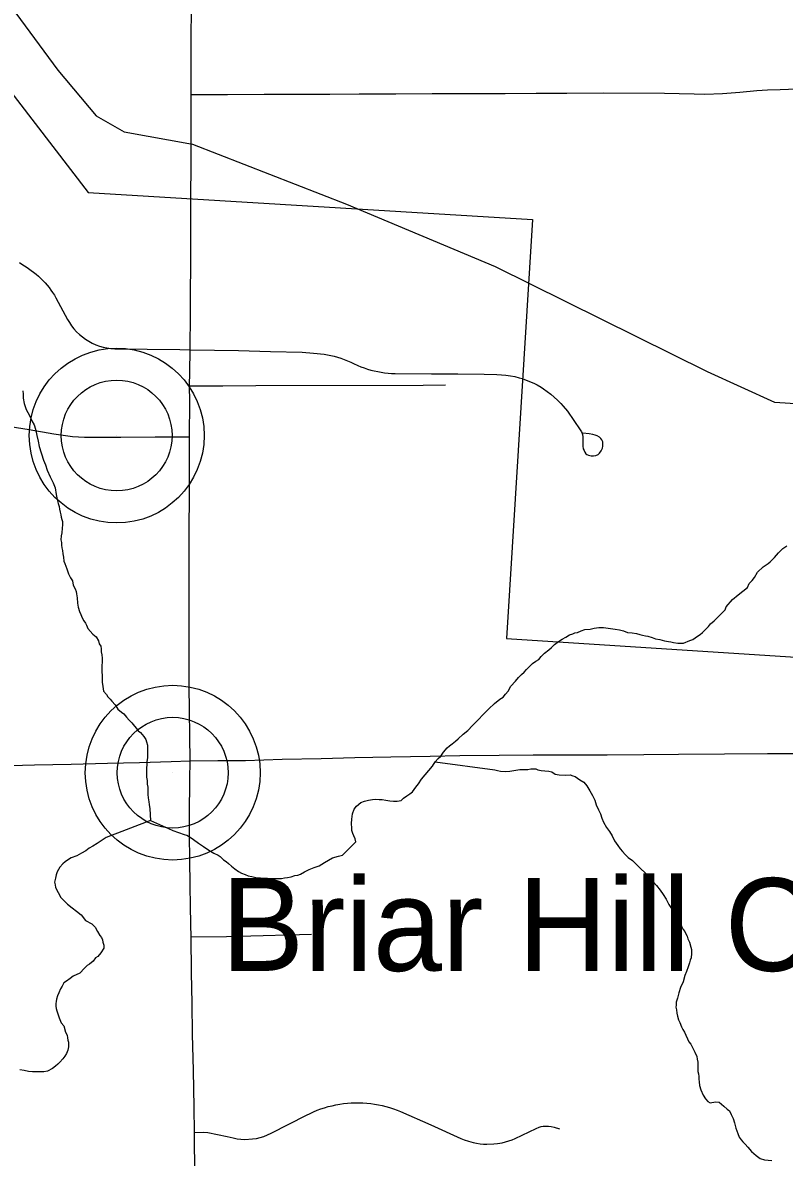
# Model space of a CAD drawing. Extents: x -11.4 to 84.1, y 11.1 to 59.
# Drawn here: x 28.325 to 28.973, y 45.628 to 46.596 of the extents above; entities that cross this region are included whole.
import ezdxf

# ---------------------------------------------------------------- set-up
doc = ezdxf.new("R2010")
doc.units = 0
for name, color, linetype in [('GM_X_Corporation', 7, 'Continuous'), ('GM_X_County_Road', 7, 'Continuous'), ('GM_X_Major_River', 7, 'Continuous'), ('GM_X_Minor_River', 7, 'Continuous'), ('GM_X_Rail_Line', 7, 'Continuous'), ('GM_X_State_Route', 7, 'Continuous'), ('GM_X_Township_Road', 7, 'Continuous'), ('GM_X_Unincorporated', 7, 'Continuous'), ('GM_X_Unincorporated_Location', 7, 'Continuous'), ('GM_X_Unincorporated_Text', 7, 'Continuous')]:
    doc.layers.add(name, color=color, linetype=linetype)

msp = doc.modelspace()

# ---------------------------------------------------------------- linework, layer by layer
at = {"layer": 'GM_X_Corporation'}
msp.add_lwpolyline([(28.25971, 46.6087), (28.38036, 46.45198), (28.75842, 46.42895), (28.73636, 46.07221), (29.25462, 46.0387), (29.28069, 46.4633), (29.48694, 46.4478)], dxfattribs=at)
at = {"layer": 'GM_X_County_Road'}
for points in [[(28.4671, 45.96801), (28.49064, 45.96824), (28.51419, 45.96847), (28.54524, 45.96936), (28.57848, 45.97013), (28.60711, 45.97079), (28.63782, 45.97132), (28.6713, 45.9719), (28.69658, 45.97255), (28.73007, 45.97288), (28.75893, 45.97317), (28.79056, 45.97306), (28.82196, 45.97317), (28.85314, 45.97352), (28.88269, 45.97363), (28.92183, 45.97387), (28.95842, 45.97421), (28.9926, 45.97437)], [(28.30368, 45.96376), (28.33474, 45.96453), (28.36579, 45.9653), (28.39685, 45.96608), (28.42385, 45.96675), (28.45086, 45.96742), (28.4671, 45.96801)]]:
    msp.add_lwpolyline(points, dxfattribs=at)
at = {"layer": 'GM_X_Major_River'}
for points in [[(28.67555, 45.96706), (28.67815, 45.97015), (28.6804, 45.97209), (28.68262, 45.97554), (28.6856, 45.97902), (28.68785, 45.98095), (28.6901, 45.98251), (28.69272, 45.98484), (28.69497, 45.98677), (28.69946, 45.99065), (28.70321, 45.99376), (28.70731, 45.998), (28.71179, 46.00264), (28.71665, 46.00767), (28.72113, 46.0123), (28.72599, 46.01695), (28.73049, 46.02044), (28.73349, 46.02239), (28.73535, 46.0247), (28.73759, 46.0274), (28.73979, 46.03162), (28.7439, 46.03587), (28.74651, 46.03896), (28.74912, 46.04166), (28.75137, 46.0436), (28.75323, 46.04591), (28.75622, 46.049), (28.75846, 46.05094), (28.76109, 46.05289), (28.76372, 46.05445), (28.76558, 46.05676), (28.76857, 46.05985), (28.77232, 46.06258), (28.77457, 46.06452), (28.77718, 46.06722), (28.78056, 46.06956), (28.78357, 46.07151), (28.78657, 46.07346), (28.78996, 46.07542), (28.7926, 46.07622), (28.79449, 46.07701), (28.79676, 46.07743), (28.79978, 46.07862), (28.8028, 46.07981), (28.80735, 46.08027), (28.81075, 46.08108), (28.81492, 46.08153), (28.81872, 46.08159), (28.82862, 46.08024), (28.83243, 46.07954), (28.83586, 46.07883), (28.8393, 46.07737), (28.84311, 46.07705), (28.84692, 46.07635), (28.84959, 46.07564), (28.85188, 46.07491), (28.85454, 46.07458), (28.85645, 46.07423), (28.86026, 46.07315), (28.86294, 46.07206), (28.86675, 46.07136), (28.87057, 46.07028), (28.874, 46.06957), (28.8759, 46.06923), (28.87819, 46.06888), (28.882, 46.06818), (28.88428, 46.06822), (28.88693, 46.06827), (28.89221, 46.07063), (28.89486, 46.07144), (28.89861, 46.07416), (28.90086, 46.07572), (28.90311, 46.07728), (28.90498, 46.07921), (28.90797, 46.0823), (28.90983, 46.08461), (28.91282, 46.08732), (28.91582, 46.09004), (28.91768, 46.09197), (28.91955, 46.0939), (28.92216, 46.0966), (28.92325, 46.09928), (28.92847, 46.10545), (28.93334, 46.10934), (28.94122, 46.11555), (28.94268, 46.119), (28.94529, 46.1217), (28.94715, 46.12401), (28.94973, 46.12862), (28.95459, 46.13326), (28.95872, 46.13599), (28.9606, 46.13754), (28.96247, 46.13948), (28.96434, 46.14103), (28.96768, 46.14527), (28.97143, 46.14875), (28.9748, 46.15109)], [(28.43346, 45.91734), (28.4486, 45.91047), (28.45243, 45.90863), (28.46198, 45.90537), (28.46427, 45.90465), (28.46695, 45.90317), (28.47003, 45.90094), (28.47426, 45.89797), (28.47849, 45.895), (28.48309, 45.89203), (28.48732, 45.88944), (28.49076, 45.88759), (28.49268, 45.88648), (28.49539, 45.88387), (28.49769, 45.88238), (28.49962, 45.88051), (28.50232, 45.87827), (28.50501, 45.87604), (28.50809, 45.87381), (28.51077, 45.87233), (28.51383, 45.87124), (28.5165, 45.87014), (28.51956, 45.86943), (28.52299, 45.86873), (28.52679, 45.86841), (28.53287, 45.86813), (28.53668, 45.86781), (28.54237, 45.86791), (28.54465, 45.86794), (28.5473, 45.86837), (28.54995, 45.86879), (28.55298, 45.86922), (28.556, 45.87041), (28.55866, 45.87084), (28.56092, 45.87163), (28.56431, 45.87359), (28.56845, 45.87556), (28.5726, 45.87715), (28.57675, 45.87874), (28.58127, 45.88148), (28.58804, 45.88539), (28.59333, 45.887), (28.59673, 45.88781), (28.60794, 45.89902), (28.60752, 45.90168), (28.60633, 45.90432), (28.60554, 45.90621), (28.60474, 45.90886), (28.6047, 45.91076), (28.60426, 45.91456), (28.60458, 45.91836), (28.60492, 45.92065), (28.60526, 45.92294), (28.60672, 45.92676), (28.60857, 45.92946), (28.61232, 45.93256), (28.61533, 45.93375), (28.61874, 45.93457), (28.62215, 45.935), (28.62518, 45.93543), (28.62785, 45.9351), (28.6305, 45.93514), (28.63355, 45.93443), (28.63698, 45.93411), (28.64002, 45.93377), (28.64306, 45.93383), (28.64647, 45.93426), (28.64872, 45.9362), (28.65134, 45.93814), (28.65397, 45.94009), (28.65622, 45.94165), (28.6592, 45.9455), (28.66143, 45.94858), (28.66402, 45.95242), (28.67333, 45.9636), (28.67555, 45.96706)], [(28.43346, 45.91734), (28.39555, 45.90276), (28.39217, 45.90042), (28.38804, 45.89769), (28.38428, 45.89535), (28.38127, 45.89378), (28.37827, 45.89145), (28.3745, 45.88948), (28.37075, 45.88714), (28.36584, 45.88554), (28.36283, 45.88359), (28.36058, 45.88203), (28.3587, 45.88048), (28.3561, 45.87739), (28.35388, 45.87355), (28.35317, 45.87088), (28.35245, 45.8682), (28.35175, 45.86477), (28.35217, 45.8625), (28.35259, 45.86022), (28.35691, 45.85155), (28.35922, 45.8493), (28.3627, 45.84594), (28.36655, 45.84296), (28.3704, 45.83998), (28.37425, 45.837), (28.37813, 45.83212), (28.38349, 45.82917), (28.38619, 45.82655), (28.38816, 45.82278), (28.39011, 45.81939), (28.39166, 45.81752), (28.39246, 45.81563), (28.39287, 45.81373), (28.39367, 45.81108), (28.39372, 45.80842), (28.39112, 45.80458), (28.38851, 45.80149), (28.38664, 45.80032), (28.3844, 45.79762), (28.38141, 45.79491), (28.37953, 45.79374), (28.37729, 45.79142), (28.37318, 45.78717), (28.36753, 45.7848), (28.3649, 45.78285), (28.3619, 45.78052), (28.35965, 45.77896), (28.35817, 45.77628), (28.35669, 45.77397), (28.35523, 45.77052), (28.35414, 45.76784), (28.35342, 45.76517), (28.35307, 45.76326), (28.35272, 45.76136), (28.35276, 45.75908), (28.35318, 45.75718), (28.35358, 45.75529), (28.35439, 45.75264), (28.35559, 45.74924), (28.35718, 45.74508), (28.3595, 45.74245), (28.36111, 45.73716), (28.36229, 45.73452), (28.36271, 45.73224), (28.36312, 45.73035), (28.36353, 45.72845), (28.3636, 45.72465), (28.36289, 45.7216), (28.36179, 45.71892), (28.36031, 45.71661), (28.35883, 45.71431), (28.35622, 45.7116), (28.35435, 45.70967), (28.35248, 45.70812), (28.34985, 45.70617), (28.34571, 45.70382), (28.34268, 45.70339), (28.33964, 45.70334), (28.33661, 45.70329), (28.33281, 45.70323), (28.32939, 45.70355), (28.32595, 45.70426), (28.32215, 45.70496)]]:
    msp.add_lwpolyline(points, dxfattribs=at)
at = {"layer": 'GM_X_Minor_River'}
for points in [[(28.3246, 46.28299), (28.32503, 46.28034), (28.32508, 46.27691), (28.32592, 46.27237), (28.32753, 46.26707), (28.33027, 46.26217), (28.33224, 46.25764), (28.3342, 46.25425), (28.3354, 46.25047), (28.33663, 46.24516), (28.33785, 46.24024), (28.33869, 46.23569), (28.3423, 46.22396), (28.34389, 46.22018), (28.34548, 46.21565), (28.34786, 46.20998), (28.3506, 46.2047), (28.35219, 46.20055), (28.35305, 46.19486), (28.35388, 46.19069), (28.35469, 46.18728), (28.3555, 46.18463), (28.35592, 46.18236), (28.35634, 46.1797), (28.35714, 46.17743), (28.35717, 46.17553), (28.35796, 46.17364), (28.35838, 46.17175), (28.35842, 46.16909), (28.35809, 46.16604), (28.35777, 46.16223), (28.35744, 46.15956), (28.35712, 46.15614), (28.35754, 46.15386), (28.35757, 46.15158), (28.35799, 46.14931), (28.35841, 46.14703), (28.35883, 46.14438), (28.35926, 46.14134), (28.3597, 46.13793), (28.36049, 46.13604), (28.36129, 46.13377), (28.36209, 46.1315), (28.36368, 46.12735), (28.36525, 46.12395), (28.36682, 46.12131), (28.36764, 46.11752), (28.36921, 46.11451), (28.37001, 46.11224), (28.37042, 46.11034), (28.37086, 46.10693), (28.37131, 46.10238), (28.37175, 46.09896), (28.37295, 46.09518), (28.37414, 46.09253), (28.37532, 46.08989), (28.3765, 46.08725), (28.37805, 46.08538), (28.37885, 46.08349), (28.38003, 46.08084), (28.38429, 46.07597), (28.38699, 46.07373), (28.38894, 46.07034), (28.38975, 46.06769), (28.39092, 46.06581), (28.39133, 46.06354), (28.39138, 46.06088), (28.3918, 46.05822), (28.39223, 46.05557), (28.39229, 46.05215), (28.39196, 46.0491), (28.392, 46.04644), (28.39205, 46.0434), (28.39209, 46.04111), (28.39214, 46.03845), (28.39219, 46.03503), (28.39264, 46.03124), (28.39305, 46.02934), (28.39346, 46.02745), (28.39579, 46.02445), (28.39696, 46.02256), (28.39889, 46.02069), (28.40044, 46.01882), (28.40315, 46.01582), (28.40549, 46.01206), (28.40858, 46.00944), (28.4105, 46.00795), (28.41282, 46.00533), (28.41515, 46.00271), (28.41746, 46.00046), (28.41979, 45.99746), (28.42134, 45.99559), (28.42289, 45.99371), (28.42482, 45.99222), (28.42753, 45.98884), (28.42948, 45.98621)], [(28.42948, 45.98621), (28.42989, 45.98432), (28.4307, 45.98129), (28.43074, 45.97901), (28.43079, 45.97559), (28.43088, 45.97064), (28.43017, 45.96759), (28.43021, 45.96493), (28.42989, 45.96188), (28.42996, 45.9577), (28.43001, 45.95428), (28.43044, 45.95124), (28.43049, 45.9482), (28.43092, 45.94555), (28.43097, 45.94251), (28.43102, 45.93946), (28.43145, 45.93643), (28.43189, 45.93302), (28.43231, 45.93074), (28.43274, 45.92732), (28.43346, 45.91734)], [(28.67555, 45.96706), (28.72618, 45.96029), (28.72846, 45.95995), (28.73113, 45.95923), (28.7357, 45.95892), (28.73911, 45.95936), (28.74744, 45.96064), (28.75086, 45.9607), (28.75428, 45.96075), (28.75693, 45.96118), (28.75921, 45.96121), (28.76111, 45.96124), (28.76302, 45.96052), (28.76569, 45.9598), (28.76873, 45.95947), (28.77216, 45.95914), (28.77482, 45.95881), (28.77752, 45.95657), (28.78094, 45.95625), (28.78626, 45.95595), (28.79044, 45.95602), (28.79273, 45.9553), (28.79464, 45.95457), (28.79849, 45.95197), (28.80194, 45.94975), (28.80465, 45.94675), (28.807, 45.94261), (28.80935, 45.93846), (28.81131, 45.93469), (28.81252, 45.93053), (28.81449, 45.92638), (28.81606, 45.92298), (28.81727, 45.9192), (28.81884, 45.9158), (28.8212, 45.91128), (28.82391, 45.9079), (28.82625, 45.90414), (28.82822, 45.89999), (28.83095, 45.89585), (28.8329, 45.89322), (28.83483, 45.89097), (28.83715, 45.88834), (28.83986, 45.88573), (28.84332, 45.88312), (28.84679, 45.87976), (28.85027, 45.87639), (28.85413, 45.87265), (28.86109, 45.86516), (28.86381, 45.86178), (28.86691, 45.85803), (28.86963, 45.85427), (28.87198, 45.85013), (28.87433, 45.84561), (28.87667, 45.84222), (28.87861, 45.83959), (28.8802, 45.83544), (28.88215, 45.83242), (28.88372, 45.82941), (28.88529, 45.82677), (28.88646, 45.82451), (28.88801, 45.82263), (28.88881, 45.82075), (28.88998, 45.81887), (28.8904, 45.81659), (28.89197, 45.81357), (28.89317, 45.80941), (28.89359, 45.80752), (28.89364, 45.80409), (28.89333, 45.80029), (28.8926, 45.79837), (28.89188, 45.79608), (28.8908, 45.79264), (28.88934, 45.78881), (28.88788, 45.78537), (28.88645, 45.78002), (28.88425, 45.77504), (28.88281, 45.77045), (28.88175, 45.76587), (28.88067, 45.76243), (28.88071, 45.76015), (28.88036, 45.75825), (28.88078, 45.75597), (28.8812, 45.75332), (28.88162, 45.75066), (28.88243, 45.74763), (28.88361, 45.74537), (28.88519, 45.74159), (28.88637, 45.73933), (28.88755, 45.73707), (28.88873, 45.73443), (28.8903, 45.73141), (28.89149, 45.72877), (28.89304, 45.72689), (28.89657, 45.72011), (28.89815, 45.71633), (28.89857, 45.71405), (28.899, 45.7114), (28.89904, 45.70874), (28.89909, 45.7057), (28.89913, 45.70342), (28.89954, 45.70152)], [(28.89954, 45.70152), (28.89996, 45.69925), (28.9, 45.69697), (28.90004, 45.69468), (28.90047, 45.69165), (28.90167, 45.68787), (28.90364, 45.68334), (28.90559, 45.68033), (28.90753, 45.67808), (28.90945, 45.67697), (28.91399, 45.6778), (28.91704, 45.67747), (28.92127, 45.67412), (28.92397, 45.6715), (28.9259, 45.67001), (28.92747, 45.667), (28.92904, 45.6636), (28.93025, 45.65982), (28.93146, 45.65527), (28.93306, 45.65074), (28.93425, 45.64772), (28.9358, 45.64546), (28.93736, 45.64358), (28.93929, 45.64171), (28.94161, 45.63909), (28.94471, 45.63534), (28.94856, 45.63198), (28.95203, 45.62938), (28.95584, 45.6283), (28.96193, 45.62764)]]:
    msp.add_lwpolyline(points, dxfattribs=at)
at = {"layer": 'GM_X_Rail_Line'}
msp.add_lwpolyline([(27.87133, 47.41026), (28.31469, 46.60998), (28.35442, 46.5561), (28.38709, 46.51724), (28.411, 46.50365), (28.46901, 46.49304), (28.59999, 46.44188), (28.7266, 46.38884), (28.90686, 46.29962), (28.96424, 46.27341), (29.02225, 46.26967), (29.04408, 46.28589), (29.07776, 46.34829), (29.09959, 46.38323), (29.13452, 46.40756), (29.16446, 46.41567), (29.23369, 46.40569), (29.32475, 46.39009), (29.40646, 46.38884)], dxfattribs=at)
at = {"layer": 'GM_X_State_Route'}
for points in [[(28.4671, 45.96801), (28.46678, 45.98943), (28.46646, 46.01084), (28.46632, 46.03174), (28.46617, 46.05264), (28.46627, 46.08371), (28.46636, 46.11477), (28.4664, 46.2439), (28.46666, 46.27404), (28.46662, 46.28727), (28.46686, 46.29901), (28.467, 46.31811), (28.46725, 46.34917), (28.46741, 46.36859), (28.46757, 46.38801), (28.4678, 46.5353), (28.46794, 46.56637), (28.46803, 46.58602), (28.46811, 46.60567), (28.46823, 46.61662)], [(28.47114, 45.6232), (28.47082, 45.64282), (28.47077, 45.65173), (28.47041, 45.6732), (28.46978, 45.70427), (28.46916, 45.73533), (28.46863, 45.76152), (28.46809, 45.78772), (28.46801, 45.81831), (28.46762, 45.82873), (28.4673, 45.84497), (28.46698, 45.86121), (28.46675, 45.88477), (28.46657, 45.90363), (28.46646, 45.92173), (28.46675, 45.95229), (28.4671, 45.96801)]]:
    msp.add_lwpolyline(points, dxfattribs=at)
at = {"layer": 'GM_X_Township_Road'}
for points in [[(28.4678, 46.5353), (28.49887, 46.53542), (28.52994, 46.53554), (28.56101, 46.53566), (28.58595, 46.53576), (28.61088, 46.53585), (28.64195, 46.53598), (28.67302, 46.53609), (28.70409, 46.53622), (28.73516, 46.53634), (28.76135, 46.53644), (28.78755, 46.53654), (28.81861, 46.53666), (28.87065, 46.53655), (28.88327, 46.53631), (28.89598, 46.53606)], [(28.89598, 46.53606), (28.90492, 46.53575), (28.92003, 46.53619), (28.93463, 46.53743), (28.94923, 46.53874), (28.95828, 46.5394), (28.96909, 46.53969), (28.98336, 46.54007)], [(28.32192, 46.39231), (28.32467, 46.3904), (28.32742, 46.38859), (28.32964, 46.38715), (28.33182, 46.38564), (28.3339, 46.38405), (28.33599, 46.38237), (28.33798, 46.38063), (28.33992, 46.37883), (28.34176, 46.37696), (28.34357, 46.37502), (28.34532, 46.37302), (28.34698, 46.37097), (28.34854, 46.36885), (28.35005, 46.36668), (28.35152, 46.36446), (28.35289, 46.36219), (28.36274, 46.34389), (28.3643, 46.34119), (28.36615, 46.33844), (28.36818, 46.33585), (28.37041, 46.33338), (28.37278, 46.33108), (28.37534, 46.32896), (28.37799, 46.32702), (28.38079, 46.32528), (28.38372, 46.32372), (28.38675, 46.32237), (28.38988, 46.32124), (28.39305, 46.32033), (28.39628, 46.31965), (28.39954, 46.31919), (28.40286, 46.31896), (28.43055, 46.31865), (28.45825, 46.31834), (28.467, 46.31811)], [(28.467, 46.31811), (28.48767, 46.31775), (28.50833, 46.3174), (28.53539, 46.31666), (28.56246, 46.31593), (28.57205, 46.31515), (28.57503, 46.31496), (28.57797, 46.31468), (28.58095, 46.3143), (28.58384, 46.3138), (28.58678, 46.3132), (28.58967, 46.31252), (28.59252, 46.31172), (28.59536, 46.31082), (28.59815, 46.30982), (28.60095, 46.30874), (28.60365, 46.30755), (28.60597, 46.30645), (28.60962, 46.30476), (28.61236, 46.30362), (28.61516, 46.30258), (28.61796, 46.30164), (28.62085, 46.30079), (28.62368, 46.30005), (28.62662, 46.2994), (28.62951, 46.29886), (28.63245, 46.29841), (28.63543, 46.29808), (28.63837, 46.29784), (28.64136, 46.29771), (28.67243, 46.29754), (28.69488, 46.29741), (28.71734, 46.29728), (28.72811, 46.29691), (28.73195, 46.29677), (28.73574, 46.29644), (28.73953, 46.2959), (28.74327, 46.29518), (28.74696, 46.29425), (28.74943, 46.29353), (28.75303, 46.29228), (28.75658, 46.29085), (28.76004, 46.28924), (28.76231, 46.28805), (28.76558, 46.28614), (28.76776, 46.28478), (28.77089, 46.28258), (28.77387, 46.28023), (28.77676, 46.27773), (28.77951, 46.27507), (28.78233, 46.27228), (28.78441, 46.26998), (28.78804, 46.2657), (28.79901, 46.24984), (28.80005, 46.24803), (28.80076, 46.24589), (28.80106, 46.2438), (28.80118, 46.24065), (28.80108, 46.23782), (28.8012, 46.23607), (28.80159, 46.23377), (28.80219, 46.23218), (28.80274, 46.23097), (28.80371, 46.22953), (28.80466, 46.22878), (28.80609, 46.22817), (28.80828, 46.22779), (28.81015, 46.22768), (28.8122, 46.22787), (28.81426, 46.22888), (28.8154, 46.2299), (28.81688, 46.23197), (28.81786, 46.23431), (28.81827, 46.23607), (28.81805, 46.23958), (28.81733, 46.24134), (28.81642, 46.24252), (28.8153, 46.2437), (28.81327, 46.24485), (28.81157, 46.24545), (28.80967, 46.24601), (28.80664, 46.24641), (28.80104, 46.24693)], [(28.46662, 46.28727), (28.49477, 46.28738), (28.52292, 46.28749), (28.66533, 46.28789), (28.6843, 46.28806)], [(28.30689, 46.25392), (28.33, 46.25017), (28.35098, 46.24646), (28.36687, 46.24414), (28.37711, 46.24355), (28.40818, 46.24367), (28.43729, 46.24378), (28.4664, 46.2439)], [(28.46801, 45.81831), (28.49806, 45.81842), (28.52912, 45.81934), (28.54976, 45.81995), (28.5704, 45.82056)], [(28.47077, 45.65173), (28.47833, 45.65184), (28.48211, 45.65161), (28.49853, 45.64818), (28.50371, 45.64697), (28.50693, 45.64634), (28.51025, 45.64593), (28.51352, 45.64576), (28.52015, 45.6461), (28.52342, 45.64661), (28.52664, 45.64735), (28.52976, 45.64831), (28.53285, 45.64949), (28.53607, 45.65098), (28.55109, 45.65871), (28.56611, 45.66644), (28.5691, 45.6679), (28.57214, 45.66926), (28.57517, 45.67051), (28.57829, 45.67164), (28.58142, 45.67268), (28.58459, 45.6736), (28.58782, 45.67442), (28.59104, 45.67511), (28.59431, 45.6757), (28.59758, 45.67617), (28.60085, 45.67653), (28.60417, 45.67678), (28.60744, 45.6769), (28.61407, 45.67681), (28.61738, 45.67659), (28.62065, 45.67626), (28.62392, 45.67581), (28.62719, 45.67524), (28.63041, 45.67456), (28.63363, 45.67378), (28.63681, 45.67287), (28.63998, 45.67187), (28.64311, 45.67074), (28.64614, 45.66952), (28.67182, 45.65806), (28.69749, 45.6466), (28.70024, 45.64546), (28.70398, 45.64416), (28.70782, 45.64312), (28.71075, 45.64253), (28.71369, 45.64209), (28.71663, 45.64179), (28.71961, 45.64166), (28.72558, 45.64186), (28.72852, 45.64219), (28.73246, 45.64288), (28.73535, 45.64357), (28.73818, 45.64441), (28.74098, 45.6454), (28.74373, 45.64653), (28.76147, 45.65497), (28.76411, 45.65604), (28.76569, 45.65663), (28.76748, 45.65691), (28.76894, 45.65704), (28.77191, 45.65697), (28.77421, 45.65675), (28.77683, 45.65628), (28.78139, 45.65476)]]:
    msp.add_lwpolyline(points, dxfattribs=at)
at = {"layer": 'GM_X_Unincorporated'}
for centre, radius in [((28.40455, 46.245), 0.0744), ((28.40455, 46.245), 0.04716), ((28.45221, 45.95793), 0.0744), ((28.45221, 45.95793), 0.04716)]:
    msp.add_circle(centre, radius, dxfattribs=at)
at = {"layer": 'GM_X_Unincorporated_Location'}
for p, q in [((28.40455, 46.245), (28.40455, 46.245)), ((28.45221, 45.95793), (28.45221, 45.95793))]:
    msp.add_line(p, q, dxfattribs=at)

# ---------------------------------------------------------------- texts
at = {"layer": 'GM_X_Unincorporated_Text'}
msp.add_text('Briar Hill Corners', height=0.0789773, rotation=0.00001, dxfattribs=at).set_placement((28.49354, 45.78918))

doc.saveas('drawing.dxf')
